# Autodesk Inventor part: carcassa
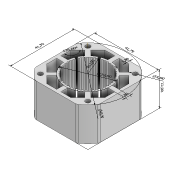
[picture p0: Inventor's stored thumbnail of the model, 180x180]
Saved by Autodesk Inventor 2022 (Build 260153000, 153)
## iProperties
Created: 2021-04
Part Number: carcassa
Material: Generico
Document SubType Name: Modeling
Designer: admin
Density: 1 g/cm^3
Appearance: Default
Author: admin
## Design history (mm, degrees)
node "Annotazioni"
  node "Quota lineare 1" dims "d4" = 41.7899 (derived)
  node "Quota lineare 2" dims "d7" = 41.7899 (derived)
  node "Quota diametro 1" dims "d9" = 29 (derived)
  node "Quota radiale 1" dims "d11" = 13 (derived)
  node "Quota diametro 2" dims "d13" = 3 (derived)
  node "Quota lineare 3" dims "d16" = 1.89495 (derived)
  node "Quota lineare 4" dims "d19" = 2.8 (derived)
  node "Quota angolare 1" dims "d22" = 135 deg (derived)
  node "Quota diametro 3" dims "d24" = 49.7899 (derived)
  node "Quota lineare 5" dims "d26" = 22 (derived)
sketch "Schizzo1"
  geometry: L1 (-20.895, -12.649)-(-20.895, 12.649); L2 (-14.432, 1.4)-(-19, 1.4); L3 (-13.677, 4.815)-(-12.262, 4.317); L4 (-19, 7.87)-(-19, 1.4); L5 (20.895, 12.649)-(20.895, -12.649); L6 (14.432, -1.4)-(19, -1.4); L7 (13.677, -4.815)-(12.262, -4.317); L8 (19, -7.87)-(19, -1.4); L9 (-14.425, 12.445)-(-11.195, 9.215); L10 (-11.723, 5.618)-(-13.076, 6.266); L11 (-14.425, 12.445)-(-19, 7.87); L12 (1.4, 14.432)-(1.4, 19); L13 (7.87, 19)-(1.4, 19); L14 (4.815, 13.677)-(4.317, 12.262); L15 (5.618, 11.723)-(6.266, 13.076); L16 (12.445, 14.425)-(7.87, 19); L17 (-1.4, 19)-(-1.4, 14.432); L18 (-12.649, 20.895)-(12.649, 20.895); L19 (19, 1.4)-(14.432, 1.4); L20 (-4.815, -13.677)-(-4.317, -12.262); L21 (-5.618, -11.723)-(-6.266, -13.076); L22 (-12.445, -14.425)-(-9.215, -11.195); L23 (-1.4, -14.432)-(-1.4, -19); L24 (-7.87, -19)-(-1.4, -19); L25 (-12.445, -14.425)-(-7.87, -19); L26 (-19, -1.4)-(-19, -7.87); L27 (-19, -1.4)-(-14.432, -1.4); L28 (-12.262, -4.317)-(-13.677, -4.815); L29 (-9.215, 11.195)-(-12.445, 14.425); L30 (-6.266, 13.076)-(-5.618, 11.723); L31 (-7.87, 19)-(-12.445, 14.425); L32 (-1.4, 19)-(-7.87, 19); L33 (12.445, 14.425)-(9.215, 11.195); L34 (11.195, 9.215)-(14.425, 12.445); L35 (13.076, 6.266)-(11.723, 5.618); L36 (19, 7.87)-(14.425, 12.445); L37 (12.262, 4.317)-(13.677, 4.815); L38 (19, 1.4)-(19, 7.87); L39 (11.723, -5.618)-(13.076, -6.266); L40 (12.649, -20.895)-(-12.649, -20.895); L41 (14.425, -12.445)-(19, -7.87); L42 (14.425, -12.445)-(11.195, -9.215); L43 (6.266, -13.076)-(5.618, -11.723); L44 (4.317, -12.262)-(4.815, -13.677); L45 (1.4, -19)-(1.4, -14.432); L46 (1.4, -19)-(7.87, -19); L47 (7.87, -19)-(12.445, -14.425); L48 (9.215, -11.195)-(12.445, -14.425); L49 (-4.317, 12.262)-(-4.815, 13.677); L50 (-11.195, -9.215)-(-14.425, -12.445); L51 (-13.076, -6.266)-(-11.723, -5.618); L52 (-19, -7.87)-(-14.425, -12.445); C1 r 1.5 at (-15.5, 15.5); C2 r 1.5 at (15.5, 15.5); C3 r 1.5 at (15.5, -15.5); C4 r 1.5 at (-15.5, -15.5); A1 r 0.5 centre (-12.897, 1.629) between (-12.825, 2.124) and (-12.951, 1.132); A2 r 0.5 centre (-12.592, 3.233) between (-12.458, 3.715) and (-12.707, 2.746); A3 r 13 centre (0, 0) between (-12.262, 4.317) and (-12.458, 3.715); A4 r 14.5 centre (0, 0) between (-13.677, 4.815) and (-14.432, 1.4); A5 r 13 centre (0, 0) between (-12.707, 2.746) and (-12.825, 2.124); A6 r 13 centre (0, 0) between (12.951, -1.132) and (12.99, -0.5); A7 r 0.5 centre (12.897, -1.629) between (12.825, -2.124) and (12.951, -1.132); A8 r 13 centre (0, 0) between (12.707, -2.746) and (12.825, -2.124); A9 r 0.5 centre (12.592, -3.233) between (12.458, -3.715) and (12.707, -2.746); A10 r 14.5 centre (0, 0) between (13.677, -4.815) and (14.432, -1.4); A11 r 13 centre (0, 0) between (12.262, -4.317) and (12.458, -3.715); A12 r 0.5 centre (-10.272, 7.968) between (-9.958, 8.357) and (-10.571, 7.567); A13 r 13 centre (0, 0) between (-9.539, 8.832) and (-9.958, 8.357); A14 r 13 centre (0, 0) between (-10.571, 7.567) and (-10.927, 7.043); A15 r 13 centre (0, 0) between (-11.436, 6.182) and (-11.723, 5.618); A16 r 0.5 centre (-11.19, 6.618) between (-10.927, 7.043) and (-11.436, 6.182); A17 r 2.895 centre (-18, 12.649) between (-20.369, 14.314) and (-20.895, 12.649); A18 r 14.5 centre (0, 0) between (-11.195, 9.215) and (-13.076, 6.266); A19 r 0.5 centre (1.629, 12.897) between (2.124, 12.825) and (1.132, 12.951); A20 r 13 centre (0, 0) between (2.746, 12.707) and (2.124, 12.825); A21 r 0.5 centre (3.233, 12.592) between (3.715, 12.458) and (2.746, 12.707); A22 r 14.5 centre (0, 0) between (4.815, 13.677) and (1.4, 14.432); A23 r 13 centre (0, 0) between (4.317, 12.262) and (3.715, 12.458); A24 r 13 centre (0, 0) between (6.182, 11.436) and (5.618, 11.723); A25 r 0.5 centre (6.618, 11.19) between (7.043, 10.927) and (6.182, 11.436); A26 r 13 centre (0, 0) between (7.567, 10.571) and (7.043, 10.927); A27 r 0.5 centre (7.968, 10.272) between (8.357, 9.958) and (7.567, 10.571); A28 r 14.5 centre (0, 0) between (9.215, 11.195) and (6.266, 13.076); A29 r 13 centre (0, 0) between (1.132, 12.951) and (0.5, 12.99); A30 r 0.5 centre (0, -13) between (-0.5, -12.99) and (0.5, -12.99); A31 r 13 centre (0, 0) between (-1.132, -12.951) and (-0.5, -12.99); A32 r 0.5 centre (-1.629, -12.897) between (-2.124, -12.825) and (-1.132, -12.951); A33 r 13 centre (0, 0) between (-2.746, -12.707) and (-2.124, -12.825); A34 r 0.5 centre (-3.233, -12.592) between (-3.715, -12.458) and (-2.746, -12.707); A35 r 13 centre (0, 0) between (-4.317, -12.262) and (-3.715, -12.458); A36 r 14.5 centre (0, 0) between (-4.815, -13.677) and (-1.4, -14.432); A37 r 14.5 centre (0, 0) between (-9.215, -11.195) and (-6.266, -13.076); A38 r 0.5 centre (-9.192, -9.192) between (-9.539, -8.832) and (-8.832, -9.539); A39 r 13 centre (0, 0) between (-8.832, -9.539) and (-8.357, -9.958); A40 r 0.5 centre (-7.968, -10.272) between (-8.357, -9.958) and (-7.567, -10.571); A41 r 13 centre (0, 0) between (-7.567, -10.571) and (-7.043, -10.927); A42 r 0.5 centre (-6.618, -11.19) between (-7.043, -10.927) and (-6.182, -11.436); A43 r 13 centre (0, 0) between (-6.182, -11.436) and (-5.618, -11.723); A44 r 0.5 centre (-13, 0) between (-12.99, 0.5) and (-12.99, -0.5); A45 r 13 centre (0, 0) between (-12.99, -0.5) and (-12.951, -1.132); A46 r 0.5 centre (-12.897, -1.629) between (-12.951, -1.132) and (-12.825, -2.124); A47 r 13 centre (0, 0) between (-12.825, -2.124) and (-12.707, -2.746); A48 r 0.5 centre (-12.592, -3.233) between (-12.707, -2.746) and (-12.458, -3.715); A49 r 13 centre (0, 0) between (-12.458, -3.715) and (-12.262, -4.317); A50 r 14.5 centre (0, 0) between (-14.432, -1.4) and (-13.677, -4.815); A51 r 13 centre (0, 0) between (-12.951, 1.132) and (-12.99, 0.5); A52 r 2.895 centre (-12.649, 18) between (-12.649, 20.895) and (-14.314, 20.369); A53 r 24.895 centre (0, 0) between (-14.314, 20.369) and (-20.369, 14.314); A54 r 13 centre (0, 0) between (-8.357, 9.958) and (-8.832, 9.539); A55 r 0.5 centre (-7.968, 10.272) between (-7.567, 10.571) and (-8.357, 9.958); A56 r 13 centre (0, 0) between (-7.043, 10.927) and (-7.567, 10.571); A57 r 0.5 centre (-6.618, 11.19) between (-6.182, 11.436) and (-7.043, 10.927); A58 r 13 centre (0, 0) between (-5.618, 11.723) and (-6.182, 11.436); A59 r 14.5 centre (0, 0) between (-6.266, 13.076) and (-9.215, 11.195); A60 r 0.5 centre (-9.192, 9.192) between (-8.832, 9.539) and (-9.539, 8.832); A61 r 13 centre (0, 0) between (8.832, 9.539) and (8.357, 9.958); A62 r 2.895 centre (12.649, 18) between (14.314, 20.369) and (12.649, 20.895); A63 r 24.895 centre (0, 0) between (20.369, 14.314) and (14.314, 20.369); A64 r 2.895 centre (18, 12.649) between (20.895, 12.649) and (20.369, 14.314)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; 2 further points
  constraints: 232 point on circle, 120 centre point, 104 end point
extrude "Estrusione1" new body sketch "Schizzo1" distance "d0" = 22; taper "d1" = 0 deg
node "Asse di lavoro1"
node "Solido1"
other parameters: "d10" = 51.03729 (derived), "d12" = 37.85607 (derived), "d14" = 4.55417 (derived), "d15" = 3.28187 (derived), "d17" = 6.40878 (derived), "d18" = 3.59122 (derived), "d2" = 7.50196 (derived), "d20" = 7.89909 (derived), "d21" = 4.0191 (derived), "d23" = 24.86745 (derived), "d25" = 4.38843 (derived), "d3" = 2.12909 (derived), "d5" = 2.26744 (derived), "d6" = 6.90241 (derived), "d8" = 35.30076 (derived)
